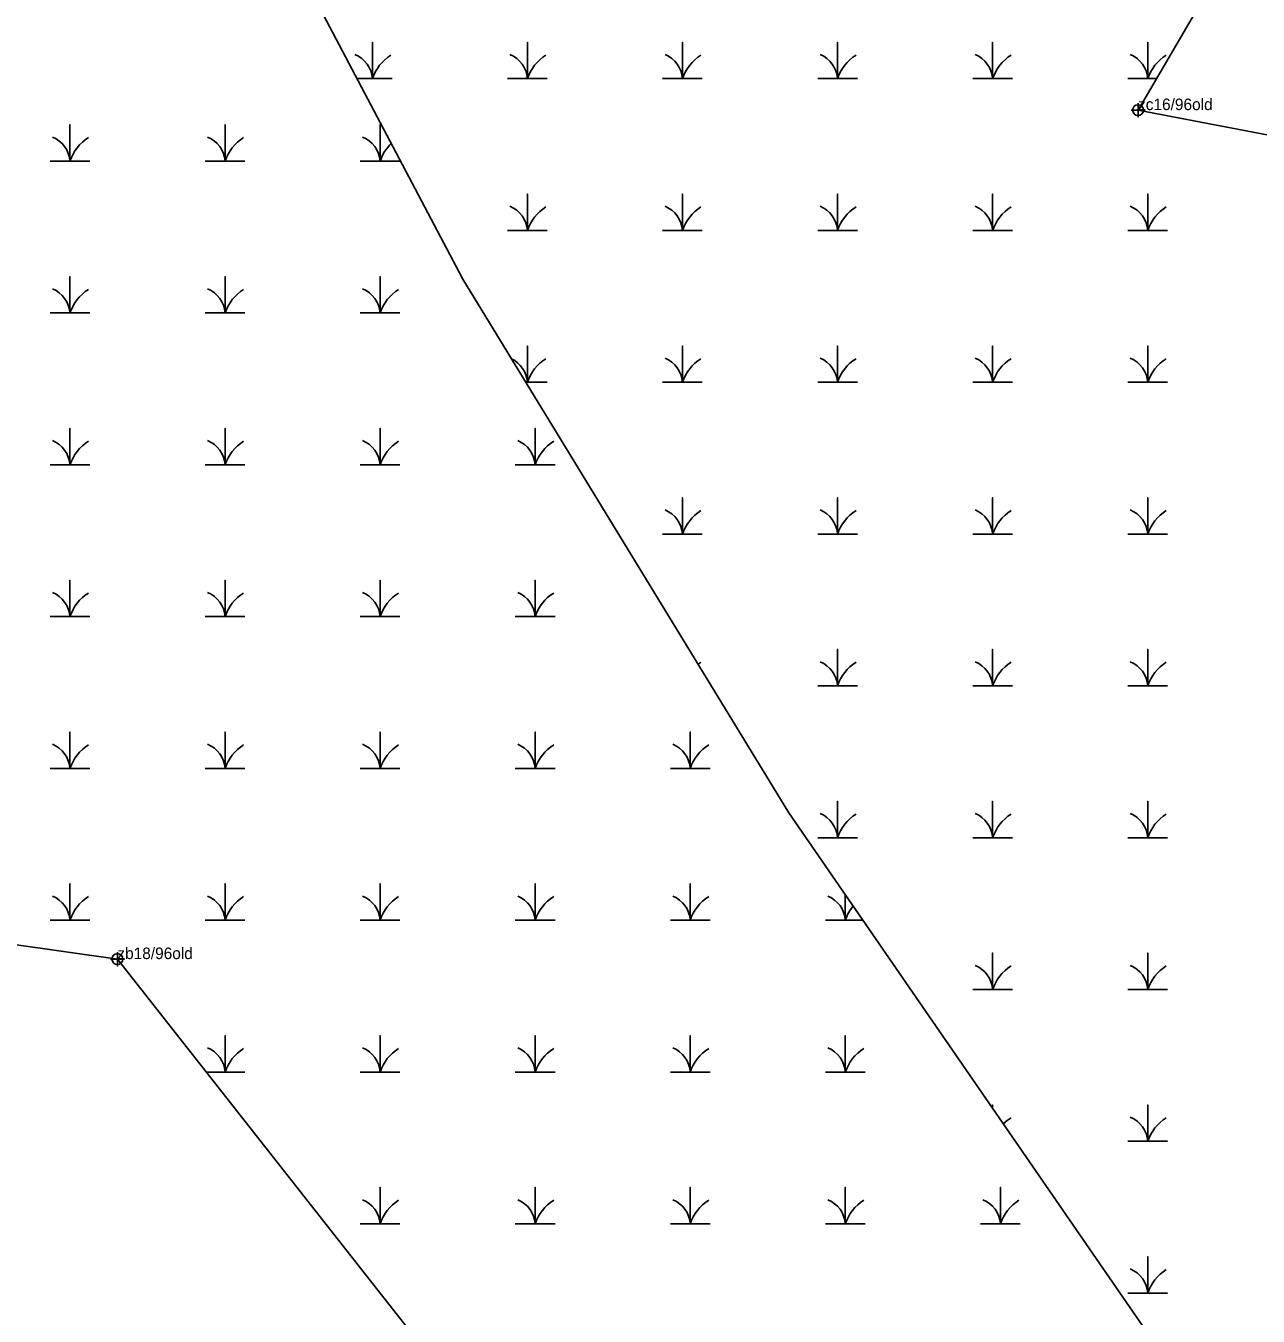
# Model space of a CAD drawing. Extents: x 2071991 to 2268989, y 436479 to 469629.
# Drawn here: x 2251679 to 2252213, y 438675 to 439235 of the extents above; entities that cross this region are included whole.
import ezdxf

# ---------------------------------------------------------------- set-up
doc = ezdxf.new("R2010")
doc.units = 0
for name, color, linetype in [('Exist Environmental Wetland Boundary', 7, 'Continuous'), ('Exist Environmental Wetland Boundary Cogo Comment', 7, 'Continuous'), ('Exist Environmental Wetland Boundary Cogo Point CELL', 7, 'Continuous'), ('Exist Hydro Jurisdictional Stream or Body of Water NEU Mitigable', 7, 'Continuous'), ('Exist Hydro Swamp or Marsh', 7, 'Continuous')]:
    doc.layers.add(name, color=color, linetype=linetype)

msp = doc.modelspace()

# ---------------------------------------------------------------- linework, layer by layer
at = {"layer": 'Exist Environmental Wetland Boundary'}
for points in [[(2251812.75, 439761.25), (2251815.72, 439741.65), (2251835.19, 439691.91), (2251853.74, 439684.4), (2251948.52, 439697.28), (2251987.54, 439620.01), (2252099.42, 439497.65), (2252162.16, 439451.4), (2252099.94, 439326.86), (2252116.54, 439273.89), (2252188.67, 439244.85), (2252161.15, 439198), (2252248.81, 439181.19), (2252288.72, 439140.38), (2252325.52, 439129.57), (2252391.77, 439077.88), (2252355.12, 439042.02), (2252453.62, 438913.56), (2252501.28, 438938.99), (2252602.41, 438934.42), (2252617.06, 438839.42), (2252682.76, 438724.15), (2252702.34, 438698.78), (2252666.6, 438658.16)], [(2251159.61, 439601.08), (2251261.98, 439510.93), (2251353.72, 439431.67), (2251408.06, 439276.46), (2251418.5, 439100.24), (2251356.47, 439015.14), (2251265.14, 438865.12), (2251366.82, 438844.78), (2251385.46, 438875.42), (2251556.91, 438853.1), (2251718.82, 438830.13), (2251868.44, 438639.97), (2251940.74, 438572.89), (2252098.49, 438426.72), (2252083.03, 438409.31), (2252090.25, 438402.8), (2252096.84, 438411.38), (2252129.61, 438370.68)]]:
    msp.add_lwpolyline(points, dxfattribs=at)
at = {"layer": 'Exist Environmental Wetland Boundary Cogo Point CELL'}
for points in [[(2252161.15, 439201), (2252161.15, 439195), (2252161.15, 439198), (2252164.15, 439198), (2252158.15, 439198)], [(2251718.82, 438833.13), (2251718.82, 438827.13), (2251718.82, 438830.13), (2251721.82, 438830.13), (2251715.82, 438830.13)]]:
    msp.add_lwpolyline(points, dxfattribs=at)
for centre in [(2252161.15, 439198), (2251718.82, 438830.13)]:
    msp.add_circle(centre, 2.34, dxfattribs=at)
at = {"layer": 'Exist Hydro Jurisdictional Stream or Body of Water NEU Mitigable'}
for p, q in [((2251746.6, 439355.93), (2251868.56, 439124.69)), ((2251868.56, 439124.69), (2252009.78, 438893.45)), ((2252009.78, 438893.45), (2252195.92, 438623.67))]:
    msp.add_line(p, q, dxfattribs=at)
at = {"layer": 'Exist Hydro Swamp or Marsh'}
for points in [[(2251822.7, 439211.63), (2251829.33, 439211.63), (2251829.33, 439227.41), (2251829.33, 439211.63), (2251837.93, 439211.63)], [(2251887.93, 439211.63), (2251896.53, 439211.63), (2251896.53, 439227.41), (2251896.53, 439211.63), (2251905.13, 439211.63)], [(2251955.13, 439211.63), (2251963.73, 439211.63), (2251963.73, 439227.41), (2251963.73, 439211.63), (2251972.33, 439211.63)], [(2252022.33, 439211.63), (2252030.94, 439211.63), (2252030.94, 439227.41), (2252030.94, 439211.63), (2252039.54, 439211.63)], [(2252089.54, 439211.63), (2252098.14, 439211.63), (2252098.14, 439227.41), (2252098.14, 439211.63), (2252106.74, 439211.63)], [(2252156.74, 439211.63), (2252165.34, 439211.63), (2252165.34, 439227.41), (2252165.34, 439211.63), (2252169.16, 439211.63)], [(2251689.68, 439175.87), (2251698.28, 439175.87), (2251698.28, 439191.65), (2251698.28, 439175.87), (2251706.88, 439175.87)], [(2251756.88, 439175.87), (2251765.48, 439175.87), (2251765.48, 439191.65), (2251765.48, 439175.87), (2251774.08, 439175.87)], [(2251824.08, 439175.87), (2251832.69, 439175.87), (2251832.69, 439191.65), (2251832.69, 439175.87), (2251841.29, 439175.87)], [(2251887.93, 439145.85), (2251896.53, 439145.85), (2251896.53, 439161.63), (2251896.53, 439145.85), (2251905.13, 439145.85)], [(2251955.13, 439145.85), (2251963.73, 439145.85), (2251963.73, 439161.63), (2251963.73, 439145.85), (2251972.33, 439145.85)], [(2252022.33, 439145.85), (2252030.94, 439145.85), (2252030.94, 439161.63), (2252030.94, 439145.85), (2252039.54, 439145.85)], [(2252089.54, 439145.85), (2252098.14, 439145.85), (2252098.14, 439161.63), (2252098.14, 439145.85), (2252106.74, 439145.85)], [(2252156.74, 439145.85), (2252165.34, 439145.85), (2252165.34, 439161.63), (2252165.34, 439145.85), (2252173.94, 439145.85)], [(2251689.68, 439110.09), (2251698.28, 439110.09), (2251698.28, 439125.87), (2251698.28, 439110.09), (2251706.88, 439110.09)], [(2251756.88, 439110.09), (2251765.48, 439110.09), (2251765.48, 439125.87), (2251765.48, 439110.09), (2251774.08, 439110.09)], [(2251824.08, 439110.09), (2251832.69, 439110.09), (2251832.69, 439125.87), (2251832.69, 439110.09), (2251841.29, 439110.09)], [(2251895.81, 439080.07), (2251896.53, 439080.07), (2251896.53, 439095.85), (2251896.53, 439080.07), (2251905.13, 439080.07)], [(2251955.13, 439080.07), (2251963.73, 439080.07), (2251963.73, 439095.85), (2251963.73, 439080.07), (2251972.33, 439080.07)], [(2252022.33, 439080.07), (2252030.94, 439080.07), (2252030.94, 439095.85), (2252030.94, 439080.07), (2252039.54, 439080.07)], [(2252089.54, 439080.07), (2252098.14, 439080.07), (2252098.14, 439095.85), (2252098.14, 439080.07), (2252106.74, 439080.07)], [(2252156.74, 439080.07), (2252165.34, 439080.07), (2252165.34, 439095.85), (2252165.34, 439080.07), (2252173.94, 439080.07)], [(2251689.68, 439044.31), (2251698.28, 439044.31), (2251698.28, 439060.09), (2251698.28, 439044.31), (2251706.88, 439044.31)], [(2251756.88, 439044.31), (2251765.48, 439044.31), (2251765.48, 439060.09), (2251765.48, 439044.31), (2251774.08, 439044.31)], [(2251824.08, 439044.31), (2251832.69, 439044.31), (2251832.69, 439060.09), (2251832.69, 439044.31), (2251841.29, 439044.31)], [(2251891.29, 439044.31), (2251899.89, 439044.31), (2251899.89, 439060.09), (2251899.89, 439044.31), (2251908.49, 439044.31)], [(2251955.13, 439014.29), (2251963.73, 439014.29), (2251963.73, 439030.07), (2251963.73, 439014.29), (2251972.33, 439014.29)], [(2252022.33, 439014.29), (2252030.94, 439014.29), (2252030.94, 439030.07), (2252030.94, 439014.29), (2252039.54, 439014.29)], [(2252089.54, 439014.29), (2252098.14, 439014.29), (2252098.14, 439030.07), (2252098.14, 439014.29), (2252106.74, 439014.29)], [(2252156.74, 439014.29), (2252165.34, 439014.29), (2252165.34, 439030.07), (2252165.34, 439014.29), (2252173.94, 439014.29)], [(2251689.68, 438978.53), (2251698.28, 438978.53), (2251698.28, 438994.31), (2251698.28, 438978.53), (2251706.88, 438978.53)], [(2251756.88, 438978.53), (2251765.48, 438978.53), (2251765.48, 438994.31), (2251765.48, 438978.53), (2251774.08, 438978.53)], [(2251824.08, 438978.53), (2251832.69, 438978.53), (2251832.69, 438994.31), (2251832.69, 438978.53), (2251841.29, 438978.53)], [(2251891.29, 438978.53), (2251899.89, 438978.53), (2251899.89, 438994.31), (2251899.89, 438978.53), (2251908.49, 438978.53)], [(2252022.33, 438948.51), (2252030.94, 438948.51), (2252030.94, 438964.29), (2252030.94, 438948.51), (2252039.54, 438948.51)], [(2252089.54, 438948.51), (2252098.14, 438948.51), (2252098.14, 438964.29), (2252098.14, 438948.51), (2252106.74, 438948.51)], [(2252156.74, 438948.51), (2252165.34, 438948.51), (2252165.34, 438964.29), (2252165.34, 438948.51), (2252173.94, 438948.51)], [(2251689.68, 438912.75), (2251698.28, 438912.75), (2251698.28, 438928.53), (2251698.28, 438912.75), (2251706.88, 438912.75)], [(2251756.88, 438912.75), (2251765.48, 438912.75), (2251765.48, 438928.53), (2251765.48, 438912.75), (2251774.08, 438912.75)], [(2251824.08, 438912.75), (2251832.69, 438912.75), (2251832.69, 438928.53), (2251832.69, 438912.75), (2251841.29, 438912.75)], [(2251891.29, 438912.75), (2251899.89, 438912.75), (2251899.89, 438928.53), (2251899.89, 438912.75), (2251908.49, 438912.75)], [(2251958.49, 438912.75), (2251967.09, 438912.75), (2251967.09, 438928.53), (2251967.09, 438912.75), (2251975.69, 438912.75)], [(2252022.33, 438882.73), (2252030.94, 438882.73), (2252030.94, 438898.51), (2252030.94, 438882.73), (2252039.54, 438882.73)], [(2252089.54, 438882.73), (2252098.14, 438882.73), (2252098.14, 438898.51), (2252098.14, 438882.73), (2252106.74, 438882.73)], [(2252156.74, 438882.73), (2252165.34, 438882.73), (2252165.34, 438898.51), (2252165.34, 438882.73), (2252173.94, 438882.73)], [(2251689.68, 438846.97), (2251698.28, 438846.97), (2251698.28, 438862.75), (2251698.28, 438846.97), (2251706.88, 438846.97)], [(2251756.88, 438846.97), (2251765.48, 438846.97), (2251765.48, 438862.75), (2251765.48, 438846.97), (2251774.08, 438846.97)], [(2251824.08, 438846.97), (2251832.69, 438846.97), (2251832.69, 438862.75), (2251832.69, 438846.97), (2251841.29, 438846.97)], [(2251891.29, 438846.97), (2251899.89, 438846.97), (2251899.89, 438862.75), (2251899.89, 438846.97), (2251908.49, 438846.97)], [(2251958.49, 438846.97), (2251967.09, 438846.97), (2251967.09, 438862.75), (2251967.09, 438846.97), (2251975.69, 438846.97)], [(2252025.69, 438846.97), (2252034.3, 438846.97), (2252034.3, 438857.91)], [(2252034.3, 438857.91), (2252034.3, 438846.97), (2252041.85, 438846.97)], [(2252089.54, 438816.95), (2252098.14, 438816.95), (2252098.14, 438832.73), (2252098.14, 438816.95), (2252106.74, 438816.95)], [(2252156.74, 438816.95), (2252165.34, 438816.95), (2252165.34, 438832.73), (2252165.34, 438816.95), (2252173.94, 438816.95)], [(2251757.33, 438781.19), (2251765.48, 438781.19), (2251765.48, 438796.97), (2251765.48, 438781.19), (2251774.08, 438781.19)], [(2251824.08, 438781.19), (2251832.69, 438781.19), (2251832.69, 438796.97), (2251832.69, 438781.19), (2251841.29, 438781.19)], [(2251891.29, 438781.19), (2251899.89, 438781.19), (2251899.89, 438796.97), (2251899.89, 438781.19), (2251908.49, 438781.19)], [(2251958.49, 438781.19), (2251967.09, 438781.19), (2251967.09, 438796.97), (2251967.09, 438781.19), (2251975.69, 438781.19)], [(2252025.69, 438781.19), (2252034.3, 438781.19), (2252034.3, 438796.97), (2252034.3, 438781.19), (2252042.9, 438781.19)], [(2252098.14, 438765.39), (2252098.14, 438766.95), (2252098.14, 438765.39)], [(2252156.74, 438751.17), (2252165.34, 438751.17), (2252165.34, 438766.95), (2252165.34, 438751.17), (2252173.94, 438751.17)], [(2251824.08, 438715.4), (2251832.69, 438715.4), (2251832.69, 438731.19), (2251832.69, 438715.4), (2251841.29, 438715.4)], [(2251891.29, 438715.4), (2251899.89, 438715.4), (2251899.89, 438731.19), (2251899.89, 438715.4), (2251908.49, 438715.4)], [(2251958.49, 438715.4), (2251967.09, 438715.4), (2251967.09, 438731.19), (2251967.09, 438715.4), (2251975.69, 438715.4)], [(2252025.69, 438715.4), (2252034.3, 438715.4), (2252034.3, 438731.19), (2252034.3, 438715.4), (2252042.9, 438715.4)], [(2252092.9, 438715.4), (2252101.5, 438715.4), (2252101.5, 438731.19), (2252101.5, 438715.4), (2252110.1, 438715.4)], [(2252156.74, 438685.39), (2252165.34, 438685.39), (2252165.34, 438701.17), (2252165.34, 438685.39), (2252173.94, 438685.39)]]:
    msp.add_lwpolyline(points, dxfattribs=at)
for centre, radius, start, end in [((2251817.06, 439210.75), 12.3, 4.1403, 67.535), ((2251847.57, 439205.57), 19.22, 122.1274, 161.6222), ((2251884.26, 439210.75), 12.3, 4.1403, 67.535), ((2251914.77, 439205.57), 19.22, 122.1274, 161.6222), ((2251951.47, 439210.75), 12.3, 4.1403, 67.535), ((2251981.97, 439205.57), 19.22, 122.1274, 161.6222), ((2252018.67, 439210.75), 12.3, 4.1403, 67.535), ((2252049.18, 439205.57), 19.22, 122.1274, 161.6222), ((2252085.87, 439210.75), 12.3, 4.1403, 67.535), ((2252116.38, 439205.57), 19.22, 122.1274, 161.6222), ((2252153.08, 439210.75), 12.3, 4.1403, 67.535), ((2252183.58, 439205.57), 19.22, 122.1274, 161.6222), ((2251686.01, 439174.98), 12.3, 4.1403, 67.535), ((2251716.52, 439169.81), 19.22, 122.1274, 161.6222), ((2251753.22, 439174.98), 12.3, 4.1403, 67.535), ((2251783.72, 439169.81), 19.22, 122.1274, 161.6222), ((2251820.42, 439174.98), 12.3, 4.1403, 67.535), ((2251850.93, 439169.81), 19.22, 134.2885, 161.6222), ((2251884.26, 439144.96), 12.3, 4.1403, 67.535), ((2251914.77, 439139.79), 19.22, 122.1274, 161.6222), ((2251951.47, 439144.96), 12.3, 4.1403, 67.535), ((2251981.97, 439139.79), 19.22, 122.1274, 161.6222), ((2252018.67, 439144.96), 12.3, 4.1403, 67.535), ((2252049.18, 439139.79), 19.22, 122.1274, 161.6222), ((2252085.87, 439144.96), 12.3, 4.1403, 67.535), ((2252116.38, 439139.79), 19.22, 122.1274, 161.6222), ((2252153.08, 439144.96), 12.3, 4.1403, 67.535), ((2252183.58, 439139.79), 19.22, 122.1274, 161.6222), ((2251686.01, 439109.2), 12.3, 4.1403, 67.535), ((2251716.52, 439104.03), 19.22, 122.1274, 161.6222), ((2251753.22, 439109.2), 12.3, 4.1403, 67.535), ((2251783.72, 439104.03), 19.22, 122.1274, 161.6222), ((2251820.42, 439109.2), 12.3, 4.1403, 67.535), ((2251850.93, 439104.03), 19.22, 122.1274, 161.6222), ((2251884.26, 439079.18), 12.3, 4.1403, 64.4093), ((2251914.77, 439074.01), 19.22, 122.1274, 161.6222), ((2251951.47, 439079.18), 12.3, 4.1403, 67.535), ((2251981.97, 439074.01), 19.22, 122.1274, 161.6222), ((2252018.67, 439079.18), 12.3, 4.1403, 67.535), ((2252049.18, 439074.01), 19.22, 122.1274, 161.6222), ((2252085.87, 439079.18), 12.3, 4.1403, 67.535), ((2252116.38, 439074.01), 19.22, 122.1274, 161.6222), ((2252153.08, 439079.18), 12.3, 4.1403, 67.535), ((2252183.58, 439074.01), 19.22, 122.1274, 161.6222), ((2251686.01, 439043.42), 12.3, 4.1403, 67.535), ((2251716.52, 439038.25), 19.22, 122.1274, 161.6222), ((2251753.22, 439043.42), 12.3, 4.1403, 67.535), ((2251783.72, 439038.25), 19.22, 122.1274, 161.6222), ((2251820.42, 439043.42), 12.3, 4.1403, 67.535), ((2251850.93, 439038.25), 19.22, 122.1274, 161.6222), ((2251887.62, 439043.42), 12.3, 4.1403, 67.535), ((2251918.13, 439038.25), 19.22, 122.1274, 161.6222), ((2251951.47, 439013.4), 12.3, 4.1403, 67.535), ((2251981.97, 439008.23), 19.22, 122.1274, 161.6222), ((2252018.67, 439013.4), 12.3, 4.1403, 67.535), ((2252049.18, 439008.23), 19.22, 122.1274, 161.6222), ((2252085.87, 439013.4), 12.3, 4.1403, 67.535), ((2252116.38, 439008.23), 19.22, 122.1274, 161.6222), ((2252153.08, 439013.4), 12.3, 4.1403, 67.535), ((2252183.58, 439008.23), 19.22, 122.1274, 161.6222), ((2251686.01, 438977.64), 12.3, 4.1403, 67.535), ((2251716.52, 438972.47), 19.22, 122.1274, 161.6222), ((2251753.22, 438977.64), 12.3, 4.1403, 67.535), ((2251783.72, 438972.47), 19.22, 122.1274, 161.6222), ((2251820.42, 438977.64), 12.3, 4.1403, 67.535), ((2251850.93, 438972.47), 19.22, 122.1274, 161.6222), ((2251887.62, 438977.64), 12.3, 4.1403, 67.535), ((2251918.13, 438972.47), 19.22, 122.1274, 161.6222), ((2251981.97, 438942.45), 19.22, 122.1274, 126.8234), ((2252018.67, 438947.62), 12.3, 4.1403, 67.535), ((2252049.18, 438942.45), 19.22, 122.1274, 161.6222), ((2252085.87, 438947.62), 12.3, 4.1403, 67.535), ((2252116.38, 438942.45), 19.22, 122.1274, 161.6222), ((2252153.08, 438947.62), 12.3, 4.1403, 67.535), ((2252183.58, 438942.45), 19.22, 122.1274, 161.6222), ((2251686.01, 438911.86), 12.3, 4.1403, 67.535), ((2251716.52, 438906.69), 19.22, 122.1274, 161.6222), ((2251753.22, 438911.86), 12.3, 4.1403, 67.535), ((2251783.72, 438906.69), 19.22, 122.1274, 161.6222), ((2251820.42, 438911.86), 12.3, 4.1403, 67.535), ((2251850.93, 438906.69), 19.22, 122.1274, 161.6222), ((2251887.62, 438911.86), 12.3, 4.1403, 67.535), ((2251918.13, 438906.69), 19.22, 122.1274, 161.6222), ((2251954.83, 438911.86), 12.3, 4.1403, 67.535), ((2251985.33, 438906.69), 19.22, 122.1274, 161.6222), ((2252018.67, 438881.84), 12.3, 4.1403, 67.535), ((2252049.18, 438876.67), 19.22, 122.1274, 161.6222), ((2252085.87, 438881.84), 12.3, 4.1403, 67.535), ((2252116.38, 438876.67), 19.22, 122.1274, 161.6222), ((2252153.08, 438881.84), 12.3, 4.1403, 67.535), ((2252183.58, 438876.67), 19.22, 122.1274, 161.6222), ((2251686.01, 438846.08), 12.3, 4.1403, 67.535), ((2251716.52, 438840.91), 19.22, 122.1274, 161.6222), ((2251753.22, 438846.08), 12.3, 4.1403, 67.535), ((2251783.72, 438840.91), 19.22, 122.1274, 161.6222), ((2251820.42, 438846.08), 12.3, 4.1403, 67.535), ((2251850.93, 438840.91), 19.22, 122.1274, 161.6222), ((2251887.62, 438846.08), 12.3, 4.1403, 67.535), ((2251918.13, 438840.91), 19.22, 122.1274, 161.6222), ((2251954.83, 438846.08), 12.3, 4.1403, 67.535), ((2251985.33, 438840.91), 19.22, 122.1274, 161.6222), ((2252022.03, 438846.08), 12.3, 4.1403, 67.535), ((2252052.54, 438840.91), 19.22, 140.7858, 161.6222), ((2252085.87, 438816.06), 12.3, 4.1403, 67.535), ((2252116.38, 438810.89), 19.22, 122.1274, 161.6222), ((2252153.08, 438816.06), 12.3, 4.1403, 67.535), ((2252183.58, 438810.89), 19.22, 122.1274, 161.6222), ((2251753.22, 438780.3), 12.3, 4.1403, 67.535), ((2251783.72, 438775.12), 19.22, 122.1274, 161.6222), ((2251820.42, 438780.3), 12.3, 4.1403, 67.535), ((2251850.93, 438775.12), 19.22, 122.1274, 161.6222), ((2251887.62, 438780.3), 12.3, 4.1403, 67.535), ((2251918.13, 438775.12), 19.22, 122.1274, 161.6222), ((2251954.83, 438780.3), 12.3, 4.1403, 67.535), ((2251985.33, 438775.12), 19.22, 122.1274, 161.6222), ((2252022.03, 438780.3), 12.3, 4.1403, 67.535), ((2252052.54, 438775.12), 19.22, 122.1274, 161.6222), ((2252116.38, 438745.11), 19.22, 122.1274, 135.0942), ((2252153.08, 438750.28), 12.3, 4.1403, 67.535), ((2252183.58, 438745.11), 19.22, 122.1274, 161.6222), ((2251820.42, 438714.52), 12.3, 4.1403, 67.535), ((2251850.93, 438709.34), 19.22, 122.1274, 161.6222), ((2251887.62, 438714.52), 12.3, 4.1403, 67.535), ((2251918.13, 438709.34), 19.22, 122.1274, 161.6222), ((2251954.83, 438714.52), 12.3, 4.1403, 67.535), ((2251985.33, 438709.34), 19.22, 122.1274, 161.6222), ((2252022.03, 438714.52), 12.3, 4.1403, 67.535), ((2252052.54, 438709.34), 19.22, 122.1274, 161.6222), ((2252089.23, 438714.52), 12.3, 4.1403, 67.535), ((2252119.74, 438709.34), 19.22, 122.1274, 161.6222), ((2252153.08, 438684.5), 12.3, 4.1403, 67.535), ((2252183.58, 438679.33), 19.22, 122.1274, 161.6222)]:
    msp.add_arc(centre, radius, start, end, dxfattribs=at)

# ---------------------------------------------------------------- texts
at = {"layer": 'Exist Environmental Wetland Boundary Cogo Comment'}
for s, p in [('zc16/96old', (2252161.15, 439198)), ('zb18/96old', (2251718.82, 438830.13))]:
    msp.add_text(s, height=5, dxfattribs=at).set_placement(p)

doc.saveas('drawing.dxf')
